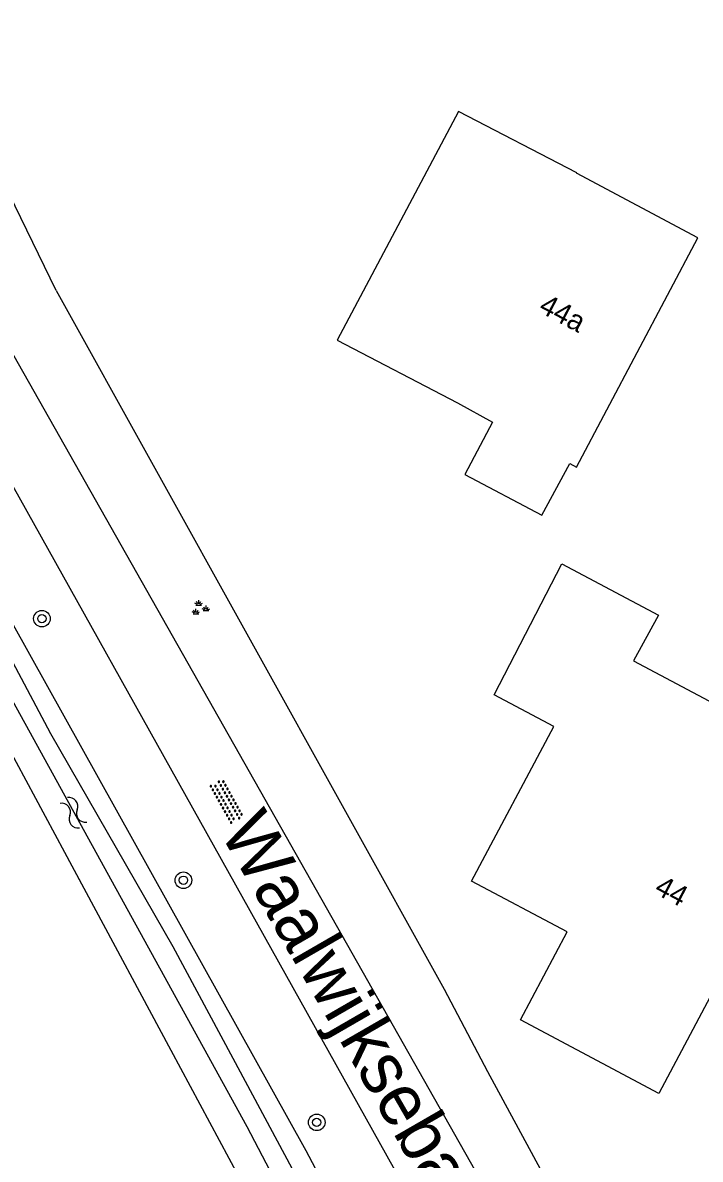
# Model space of a CAD drawing. Extents: x 136000 to 141000, y 400494 to 402006.
# Drawn here: x 137065.4 to 137098, y 400689.9 to 400744.6 of the extents above; entities that cross this region are included whole.
import ezdxf

# ---------------------------------------------------------------- set-up
doc = ezdxf.new("R2010")
doc.units = 0
for name, color, linetype in [('gg-afsc-erfafscheiding', 7, 'Continuous'), ('gg-afsc-hekwerk', 7, 'Continuous'), ('gg-anno-huisnummerreeks BGT', 7, 'Continuous'), ('gg-anno-openbare ruimte label', 7, 'Continuous'), ('gg-bbg-hoofdgebouw', 7, 'Continuous'), ('gg-knt-onverhard', 7, 'Continuous'), ('gg-kntw-bovenkant insteek waterloop', 7, 'Continuous'), ('gg-kntw-waterlijn', 7, 'Continuous'), ('gt-grn-groengrens', 7, 'Continuous'), ('gt-symb-boom', 7, 'Continuous'), ('gt-symb-groenvak', 7, 'Continuous'), ('gt-symb-overige verharding', 7, 'Continuous'), ('gt-symb-watersymbool', 7, 'Continuous')]:
    doc.layers.add(name, color=color, linetype=linetype)

# ---------------------------------------------------------------- blocks, each defined once
blk = doc.blocks.new('gt0-GRVAK')
at = {"layer": 'gt-symb-groenvak'}
for p, q in [((-0.11, 0.189), (-0.228, 0.24)), ((-0.182, 0.153), (0.088, 0.153)), ((-0.091, 0.211), (-0.156, 0.322)), ((-0.047, 0.214), (-0.047, 0.393)), ((-0.004, 0.211), (0.061, 0.322)), ((0.015, 0.189), (0.133, 0.24)), ((0.262, -0.052), (0.197, 0.059)), ((0.305, -0.049), (0.305, 0.13)), ((0.349, -0.052), (0.414, 0.059)), ((-0.245, -0.228), (-0.363, -0.177)), ((-0.318, -0.264), (-0.047, -0.264)), ((-0.226, -0.206), (-0.291, -0.095)), ((-0.183, -0.203), (-0.183, -0.024)), ((-0.139, -0.206), (-0.074, -0.095)), ((-0.12, -0.228), (-0.002, -0.177)), ((0.243, -0.074), (0.125, -0.023)), ((0.17, -0.11), (0.441, -0.11)), ((0.368, -0.074), (0.486, -0.023))]:
    blk.add_line(p, q, dxfattribs=at)
blk = doc.blocks.new('gt0-BOOM')
at = {"layer": 'gt-symb-boom'}
for radius in [0.4, 0.2]:
    blk.add_circle((0, 0), radius, dxfattribs=at)
blk = doc.blocks.new('gt0-WA')
at = {"layer": 'gt-symb-watersymbool'}
for centre, start, end in [((-0.323, 0.022), 28.0725, 151.9275), ((0.427, 0.422), 208.0725, 331.9275), ((-0.323, -0.428), 28.0725, 151.9275), ((0.427, -0.028), 208.0725, 331.9275)]:
    blk.add_arc(centre, 0.425, start, end, dxfattribs=at)
blk = doc.blocks.new('gt0-OVH')
at = {"layer": 'gt-symb-overige verharding'}
for points in [[(-0.972, 0.298), (-0.967, 0.308), (-0.965, 0.319), (-0.966, 0.33), (-0.971, 0.34), (-0.978, 0.348), (-0.988, 0.353), (-0.999, 0.355), (-1.01, 0.354), (-1.02, 0.349), (-1.028, 0.342), (-1.033, 0.332), (-1.035, 0.321), (-1.034, 0.31), (-1.029, 0.3), (-1.022, 0.292), (-1.012, 0.287), (-1.001, 0.285), (-0.99, 0.286), (-0.98, 0.291)], [(-0.872, 0.106), (-0.867, 0.116), (-0.865, 0.126), (-0.866, 0.137), (-0.871, 0.147), (-0.878, 0.156), (-0.888, 0.161), (-0.899, 0.163), (-0.91, 0.162), (-0.92, 0.157), (-0.928, 0.15), (-0.933, 0.14), (-0.935, 0.129), (-0.934, 0.118), (-0.929, 0.108), (-0.922, 0.1), (-0.912, 0.095), (-0.901, 0.092), (-0.89, 0.094), (-0.88, 0.098)], [(-0.772, 0.298), (-0.767, 0.308), (-0.765, 0.319), (-0.766, 0.33), (-0.771, 0.34), (-0.778, 0.348), (-0.788, 0.353), (-0.799, 0.355), (-0.81, 0.354), (-0.82, 0.349), (-0.828, 0.342), (-0.833, 0.332), (-0.835, 0.321), (-0.834, 0.31), (-0.829, 0.3), (-0.822, 0.292), (-0.812, 0.287), (-0.801, 0.285), (-0.79, 0.286), (-0.78, 0.291)], [(-0.672, 0.106), (-0.667, 0.116), (-0.665, 0.126), (-0.666, 0.137), (-0.671, 0.147), (-0.678, 0.156), (-0.688, 0.161), (-0.699, 0.163), (-0.71, 0.162), (-0.72, 0.157), (-0.728, 0.15), (-0.733, 0.14), (-0.735, 0.129), (-0.734, 0.118), (-0.729, 0.108), (-0.722, 0.1), (-0.712, 0.095), (-0.701, 0.092), (-0.69, 0.094), (-0.68, 0.098)], [(-0.572, 0.298), (-0.567, 0.308), (-0.565, 0.319), (-0.566, 0.33), (-0.571, 0.34), (-0.578, 0.348), (-0.588, 0.353), (-0.599, 0.355), (-0.61, 0.354), (-0.62, 0.349), (-0.628, 0.342), (-0.633, 0.332), (-0.635, 0.321), (-0.634, 0.31), (-0.629, 0.3), (-0.622, 0.292), (-0.612, 0.287), (-0.601, 0.285), (-0.59, 0.286), (-0.58, 0.291)], [(-0.472, 0.106), (-0.467, 0.116), (-0.465, 0.126), (-0.466, 0.137), (-0.471, 0.147), (-0.478, 0.156), (-0.488, 0.161), (-0.499, 0.163), (-0.51, 0.162), (-0.52, 0.157), (-0.528, 0.15), (-0.533, 0.14), (-0.535, 0.129), (-0.534, 0.118), (-0.529, 0.108), (-0.522, 0.1), (-0.512, 0.095), (-0.501, 0.092), (-0.49, 0.094), (-0.48, 0.098)], [(-0.372, 0.298), (-0.367, 0.308), (-0.365, 0.319), (-0.366, 0.33), (-0.371, 0.34), (-0.378, 0.348), (-0.388, 0.353), (-0.399, 0.355), (-0.41, 0.354), (-0.42, 0.349), (-0.428, 0.342), (-0.433, 0.332), (-0.435, 0.321), (-0.434, 0.31), (-0.429, 0.3), (-0.422, 0.292), (-0.412, 0.287), (-0.401, 0.285), (-0.39, 0.286), (-0.38, 0.291)], [(-0.272, 0.106), (-0.267, 0.116), (-0.265, 0.126), (-0.266, 0.137), (-0.271, 0.147), (-0.278, 0.156), (-0.288, 0.161), (-0.299, 0.163), (-0.31, 0.162), (-0.32, 0.157), (-0.328, 0.15), (-0.333, 0.14), (-0.335, 0.129), (-0.334, 0.118), (-0.329, 0.108), (-0.322, 0.1), (-0.312, 0.095), (-0.301, 0.092), (-0.29, 0.094), (-0.28, 0.098)], [(-0.172, 0.298), (-0.167, 0.308), (-0.165, 0.319), (-0.166, 0.33), (-0.171, 0.34), (-0.178, 0.348), (-0.188, 0.353), (-0.199, 0.355), (-0.21, 0.354), (-0.22, 0.349), (-0.228, 0.342), (-0.233, 0.332), (-0.235, 0.321), (-0.234, 0.31), (-0.229, 0.3), (-0.222, 0.292), (-0.212, 0.287), (-0.201, 0.285), (-0.19, 0.286), (-0.18, 0.291)], [(-0.072, 0.106), (-0.067, 0.116), (-0.065, 0.126), (-0.066, 0.137), (-0.071, 0.147), (-0.078, 0.156), (-0.088, 0.161), (-0.099, 0.163), (-0.11, 0.162), (-0.12, 0.157), (-0.128, 0.15), (-0.133, 0.14), (-0.135, 0.129), (-0.134, 0.118), (-0.129, 0.108), (-0.122, 0.1), (-0.112, 0.095), (-0.101, 0.092), (-0.09, 0.094), (-0.08, 0.098)], [(0.028, 0.298), (0.033, 0.308), (0.035, 0.319), (0.034, 0.33), (0.029, 0.34), (0.022, 0.348), (0.012, 0.353), (0.001, 0.355), (-0.01, 0.354), (-0.02, 0.349), (-0.028, 0.342), (-0.033, 0.332), (-0.035, 0.321), (-0.034, 0.31), (-0.029, 0.3), (-0.022, 0.292), (-0.012, 0.287), (-0.001, 0.285), (0.01, 0.286), (0.02, 0.291)], [(0.128, 0.106), (0.133, 0.116), (0.135, 0.126), (0.134, 0.137), (0.129, 0.147), (0.122, 0.156), (0.112, 0.161), (0.101, 0.163), (0.09, 0.162), (0.08, 0.157), (0.072, 0.15), (0.067, 0.14), (0.065, 0.129), (0.066, 0.118), (0.071, 0.108), (0.078, 0.1), (0.088, 0.095), (0.099, 0.092), (0.11, 0.094), (0.12, 0.098)], [(0.228, 0.298), (0.233, 0.308), (0.235, 0.319), (0.234, 0.33), (0.229, 0.34), (0.222, 0.348), (0.212, 0.353), (0.201, 0.355), (0.19, 0.354), (0.18, 0.349), (0.172, 0.342), (0.167, 0.332), (0.165, 0.321), (0.166, 0.31), (0.171, 0.3), (0.178, 0.292), (0.188, 0.287), (0.199, 0.285), (0.21, 0.286), (0.22, 0.291)], [(0.328, 0.106), (0.333, 0.116), (0.335, 0.126), (0.334, 0.137), (0.329, 0.147), (0.322, 0.156), (0.312, 0.161), (0.301, 0.163), (0.29, 0.162), (0.28, 0.157), (0.272, 0.15), (0.267, 0.14), (0.265, 0.129), (0.266, 0.118), (0.271, 0.108), (0.278, 0.1), (0.288, 0.095), (0.299, 0.092), (0.31, 0.094), (0.32, 0.098)], [(0.428, 0.298), (0.433, 0.308), (0.435, 0.319), (0.434, 0.33), (0.429, 0.34), (0.422, 0.348), (0.412, 0.353), (0.401, 0.355), (0.39, 0.354), (0.38, 0.349), (0.372, 0.342), (0.367, 0.332), (0.365, 0.321), (0.366, 0.31), (0.371, 0.3), (0.378, 0.292), (0.388, 0.287), (0.399, 0.285), (0.41, 0.286), (0.42, 0.291)], [(0.528, 0.106), (0.533, 0.116), (0.535, 0.126), (0.534, 0.137), (0.529, 0.147), (0.522, 0.156), (0.512, 0.161), (0.501, 0.163), (0.49, 0.162), (0.48, 0.157), (0.472, 0.15), (0.467, 0.14), (0.465, 0.129), (0.466, 0.118), (0.471, 0.108), (0.478, 0.1), (0.488, 0.095), (0.499, 0.092), (0.51, 0.094), (0.52, 0.098)], [(0.628, 0.298), (0.633, 0.308), (0.635, 0.319), (0.634, 0.33), (0.629, 0.34), (0.622, 0.348), (0.612, 0.353), (0.601, 0.355), (0.59, 0.354), (0.58, 0.349), (0.572, 0.342), (0.567, 0.332), (0.565, 0.321), (0.566, 0.31), (0.571, 0.3), (0.578, 0.292), (0.588, 0.287), (0.599, 0.285), (0.61, 0.286), (0.62, 0.291)], [(0.728, 0.106), (0.733, 0.116), (0.735, 0.126), (0.734, 0.137), (0.729, 0.147), (0.722, 0.156), (0.712, 0.161), (0.701, 0.163), (0.69, 0.162), (0.68, 0.157), (0.672, 0.15), (0.667, 0.14), (0.665, 0.129), (0.666, 0.118), (0.671, 0.108), (0.678, 0.1), (0.688, 0.095), (0.699, 0.092), (0.71, 0.094), (0.72, 0.098)], [(0.828, 0.298), (0.833, 0.308), (0.835, 0.319), (0.834, 0.33), (0.829, 0.34), (0.822, 0.348), (0.812, 0.353), (0.801, 0.355), (0.79, 0.354), (0.78, 0.349), (0.772, 0.342), (0.767, 0.332), (0.765, 0.321), (0.766, 0.31), (0.771, 0.3), (0.778, 0.292), (0.788, 0.287), (0.799, 0.285), (0.81, 0.286), (0.82, 0.291)], [(0.928, 0.106), (0.933, 0.116), (0.935, 0.126), (0.934, 0.137), (0.929, 0.147), (0.922, 0.156), (0.912, 0.161), (0.901, 0.163), (0.89, 0.162), (0.88, 0.157), (0.872, 0.15), (0.867, 0.14), (0.865, 0.129), (0.866, 0.118), (0.871, 0.108), (0.878, 0.1), (0.888, 0.095), (0.899, 0.092), (0.91, 0.094), (0.92, 0.098)], [(1.028, 0.298), (1.033, 0.308), (1.035, 0.319), (1.034, 0.33), (1.029, 0.34), (1.022, 0.348), (1.012, 0.353), (1.001, 0.355), (0.99, 0.354), (0.98, 0.349), (0.972, 0.342), (0.967, 0.332), (0.965, 0.321), (0.966, 0.31), (0.971, 0.3), (0.978, 0.292), (0.988, 0.287), (0.999, 0.285), (1.01, 0.286), (1.02, 0.291)], [(-0.972, -0.142), (-0.967, -0.132), (-0.965, -0.121), (-0.966, -0.11), (-0.971, -0.1), (-0.978, -0.092), (-0.988, -0.087), (-0.999, -0.085), (-1.01, -0.086), (-1.02, -0.091), (-1.028, -0.098), (-1.033, -0.108), (-1.035, -0.119), (-1.034, -0.13), (-1.029, -0.14), (-1.022, -0.148), (-1.012, -0.153), (-1.001, -0.155), (-0.99, -0.154), (-0.98, -0.149)], [(-0.872, -0.334), (-0.867, -0.324), (-0.865, -0.314), (-0.866, -0.303), (-0.871, -0.293), (-0.878, -0.284), (-0.888, -0.279), (-0.899, -0.277), (-0.91, -0.278), (-0.92, -0.283), (-0.928, -0.29), (-0.933, -0.3), (-0.935, -0.311), (-0.934, -0.322), (-0.929, -0.332), (-0.922, -0.34), (-0.912, -0.345), (-0.901, -0.348), (-0.89, -0.346), (-0.88, -0.342)], [(-0.772, -0.142), (-0.767, -0.132), (-0.765, -0.121), (-0.766, -0.11), (-0.771, -0.1), (-0.778, -0.092), (-0.788, -0.087), (-0.799, -0.085), (-0.81, -0.086), (-0.82, -0.091), (-0.828, -0.098), (-0.833, -0.108), (-0.835, -0.119), (-0.834, -0.13), (-0.829, -0.14), (-0.822, -0.148), (-0.812, -0.153), (-0.801, -0.155), (-0.79, -0.154), (-0.78, -0.149)], [(-0.672, -0.334), (-0.667, -0.324), (-0.665, -0.314), (-0.666, -0.303), (-0.671, -0.293), (-0.678, -0.284), (-0.688, -0.279), (-0.699, -0.277), (-0.71, -0.278), (-0.72, -0.283), (-0.728, -0.29), (-0.733, -0.3), (-0.735, -0.311), (-0.734, -0.322), (-0.729, -0.332), (-0.722, -0.34), (-0.712, -0.345), (-0.701, -0.348), (-0.69, -0.346), (-0.68, -0.342)], [(-0.572, -0.142), (-0.567, -0.132), (-0.565, -0.121), (-0.566, -0.11), (-0.571, -0.1), (-0.578, -0.092), (-0.588, -0.087), (-0.599, -0.085), (-0.61, -0.086), (-0.62, -0.091), (-0.628, -0.098), (-0.633, -0.108), (-0.635, -0.119), (-0.634, -0.13), (-0.629, -0.14), (-0.622, -0.148), (-0.612, -0.153), (-0.601, -0.155), (-0.59, -0.154), (-0.58, -0.149)], [(-0.472, -0.334), (-0.467, -0.324), (-0.465, -0.314), (-0.466, -0.303), (-0.471, -0.293), (-0.478, -0.284), (-0.488, -0.279), (-0.499, -0.277), (-0.51, -0.278), (-0.52, -0.283), (-0.528, -0.29), (-0.533, -0.3), (-0.535, -0.311), (-0.534, -0.322), (-0.529, -0.332), (-0.522, -0.34), (-0.512, -0.345), (-0.501, -0.348), (-0.49, -0.346), (-0.48, -0.342)], [(-0.372, -0.142), (-0.367, -0.132), (-0.365, -0.121), (-0.366, -0.11), (-0.371, -0.1), (-0.378, -0.092), (-0.388, -0.087), (-0.399, -0.085), (-0.41, -0.086), (-0.42, -0.091), (-0.428, -0.098), (-0.433, -0.108), (-0.435, -0.119), (-0.434, -0.13), (-0.429, -0.14), (-0.422, -0.148), (-0.412, -0.153), (-0.401, -0.155), (-0.39, -0.154), (-0.38, -0.149)], [(-0.272, -0.334), (-0.267, -0.324), (-0.265, -0.314), (-0.266, -0.303), (-0.271, -0.293), (-0.278, -0.284), (-0.288, -0.279), (-0.299, -0.277), (-0.31, -0.278), (-0.32, -0.283), (-0.328, -0.29), (-0.333, -0.3), (-0.335, -0.311), (-0.334, -0.322), (-0.329, -0.332), (-0.322, -0.34), (-0.312, -0.345), (-0.301, -0.348), (-0.29, -0.346), (-0.28, -0.342)], [(-0.172, -0.142), (-0.167, -0.132), (-0.165, -0.121), (-0.166, -0.11), (-0.171, -0.1), (-0.178, -0.092), (-0.188, -0.087), (-0.199, -0.085), (-0.21, -0.086), (-0.22, -0.091), (-0.228, -0.098), (-0.233, -0.108), (-0.235, -0.119), (-0.234, -0.13), (-0.229, -0.14), (-0.222, -0.148), (-0.212, -0.153), (-0.201, -0.155), (-0.19, -0.154), (-0.18, -0.149)], [(-0.072, -0.334), (-0.067, -0.324), (-0.065, -0.314), (-0.066, -0.303), (-0.071, -0.293), (-0.078, -0.284), (-0.088, -0.279), (-0.099, -0.277), (-0.11, -0.278), (-0.12, -0.283), (-0.128, -0.29), (-0.133, -0.3), (-0.135, -0.311), (-0.134, -0.322), (-0.129, -0.332), (-0.122, -0.34), (-0.112, -0.345), (-0.101, -0.348), (-0.09, -0.346), (-0.08, -0.342)], [(0.028, -0.142), (0.033, -0.132), (0.035, -0.121), (0.034, -0.11), (0.029, -0.1), (0.022, -0.092), (0.012, -0.087), (0.001, -0.085), (-0.01, -0.086), (-0.02, -0.091), (-0.028, -0.098), (-0.033, -0.108), (-0.035, -0.119), (-0.034, -0.13), (-0.029, -0.14), (-0.022, -0.148), (-0.012, -0.153), (-0.001, -0.155), (0.01, -0.154), (0.02, -0.149)], [(0.128, -0.334), (0.133, -0.324), (0.135, -0.314), (0.134, -0.303), (0.129, -0.293), (0.122, -0.284), (0.112, -0.279), (0.101, -0.277), (0.09, -0.278), (0.08, -0.283), (0.072, -0.29), (0.067, -0.3), (0.065, -0.311), (0.066, -0.322), (0.071, -0.332), (0.078, -0.34), (0.088, -0.345), (0.099, -0.348), (0.11, -0.346), (0.12, -0.342)], [(0.228, -0.142), (0.233, -0.132), (0.235, -0.121), (0.234, -0.11), (0.229, -0.1), (0.222, -0.092), (0.212, -0.087), (0.201, -0.085), (0.19, -0.086), (0.18, -0.091), (0.172, -0.098), (0.167, -0.108), (0.165, -0.119), (0.166, -0.13), (0.171, -0.14), (0.178, -0.148), (0.188, -0.153), (0.199, -0.155), (0.21, -0.154), (0.22, -0.149)], [(0.328, -0.334), (0.333, -0.324), (0.335, -0.314), (0.334, -0.303), (0.329, -0.293), (0.322, -0.284), (0.312, -0.279), (0.301, -0.277), (0.29, -0.278), (0.28, -0.283), (0.272, -0.29), (0.267, -0.3), (0.265, -0.311), (0.266, -0.322), (0.271, -0.332), (0.278, -0.34), (0.288, -0.345), (0.299, -0.348), (0.31, -0.346), (0.32, -0.342)], [(0.428, -0.142), (0.433, -0.132), (0.435, -0.121), (0.434, -0.11), (0.429, -0.1), (0.422, -0.092), (0.412, -0.087), (0.401, -0.085), (0.39, -0.086), (0.38, -0.091), (0.372, -0.098), (0.367, -0.108), (0.365, -0.119), (0.366, -0.13), (0.371, -0.14), (0.378, -0.148), (0.388, -0.153), (0.399, -0.155), (0.41, -0.154), (0.42, -0.149)], [(0.528, -0.334), (0.533, -0.324), (0.535, -0.314), (0.534, -0.303), (0.529, -0.293), (0.522, -0.284), (0.512, -0.279), (0.501, -0.277), (0.49, -0.278), (0.48, -0.283), (0.472, -0.29), (0.467, -0.3), (0.465, -0.311), (0.466, -0.322), (0.471, -0.332), (0.478, -0.34), (0.488, -0.345), (0.499, -0.348), (0.51, -0.346), (0.52, -0.342)], [(0.628, -0.142), (0.633, -0.132), (0.635, -0.121), (0.634, -0.11), (0.629, -0.1), (0.622, -0.092), (0.612, -0.087), (0.601, -0.085), (0.59, -0.086), (0.58, -0.091), (0.572, -0.098), (0.567, -0.108), (0.565, -0.119), (0.566, -0.13), (0.571, -0.14), (0.578, -0.148), (0.588, -0.153), (0.599, -0.155), (0.61, -0.154), (0.62, -0.149)], [(0.728, -0.334), (0.733, -0.324), (0.735, -0.314), (0.734, -0.303), (0.729, -0.293), (0.722, -0.284), (0.712, -0.279), (0.701, -0.277), (0.69, -0.278), (0.68, -0.283), (0.672, -0.29), (0.667, -0.3), (0.665, -0.311), (0.666, -0.322), (0.671, -0.332), (0.678, -0.34), (0.688, -0.345), (0.699, -0.348), (0.71, -0.346), (0.72, -0.342)], [(0.828, -0.142), (0.833, -0.132), (0.835, -0.121), (0.834, -0.11), (0.829, -0.1), (0.822, -0.092), (0.812, -0.087), (0.801, -0.085), (0.79, -0.086), (0.78, -0.091), (0.772, -0.098), (0.767, -0.108), (0.765, -0.119), (0.766, -0.13), (0.771, -0.14), (0.778, -0.148), (0.788, -0.153), (0.799, -0.155), (0.81, -0.154), (0.82, -0.149)], [(0.928, -0.334), (0.933, -0.324), (0.935, -0.314), (0.934, -0.303), (0.929, -0.293), (0.922, -0.284), (0.912, -0.279), (0.901, -0.277), (0.89, -0.278), (0.88, -0.283), (0.872, -0.29), (0.867, -0.3), (0.865, -0.311), (0.866, -0.322), (0.871, -0.332), (0.878, -0.34), (0.888, -0.345), (0.899, -0.348), (0.91, -0.346), (0.92, -0.342)], [(1.028, -0.142), (1.033, -0.132), (1.035, -0.121), (1.034, -0.11), (1.029, -0.1), (1.022, -0.092), (1.012, -0.087), (1.001, -0.085), (0.99, -0.086), (0.98, -0.091), (0.972, -0.098), (0.967, -0.108), (0.965, -0.119), (0.966, -0.13), (0.971, -0.14), (0.978, -0.148), (0.988, -0.153), (0.999, -0.155), (1.01, -0.154), (1.02, -0.149)]]:
    blk.add_lwpolyline(points, close=True, dxfattribs=at)

msp = doc.modelspace()

# ---------------------------------------------------------------- linework, layer by layer
at = {"layer": 'gg-afsc-erfafscheiding'}
for p, q in [((137067.029, 400731.68), (137085.715, 400698.035)), ((137087.809, 400694.083), (137093.303, 400683.93))]:
    msp.add_line(p, q, dxfattribs=at)
at = {"layer": 'gg-afsc-hekwerk'}
msp.add_line((137085.715, 400698.035), (137087.809, 400694.083), dxfattribs=at)
msp.add_line((137085.715, 400698.035), (137087.809, 400694.083), dxfattribs=at)
at = {"layer": 'gg-bbg-hoofdgebouw'}
for points in [[(137092.094, 400737.315), (137092.103, 400737.333), (137086.403, 400740.289), (137080.571, 400729.277), (137086.367, 400726.271)], [(137090.426, 400720.863), (137091.766, 400723.344), (137092.084, 400723.175), (137097.936, 400734.208), (137092.094, 400737.315)], [(137086.367, 400726.271), (137088.043, 400725.334), (137086.705, 400722.822), (137090.426, 400720.863)], [(137088.124, 400712.204), (137091.387, 400718.52), (137096.035, 400716.043), (137094.841, 400713.842), (137104.412, 400708.758), (137096.061, 400693.012), (137089.396, 400696.571)], [(137089.396, 400696.571), (137091.642, 400700.794), (137087.038, 400703.242), (137090.992, 400710.679), (137088.124, 400712.204)]]:
    msp.add_lwpolyline(points, dxfattribs=at)
at = {"layer": 'gg-knt-onverhard'}
for points in [[(137000, 400823.96), (137052.822, 400750), (137090.68, 400683.191)], [(137000, 400818.181), (137051.42, 400746.472), (137087.782, 400681.37)]]:
    msp.add_lwpolyline(points, dxfattribs=at)
at = {"layer": 'gg-kntw-bovenkant insteek waterloop'}
for points in [[(137085.81, 400670.117), (137088.609, 400672.21), (137079.08, 400690.264), (137059.918, 400724.619), (137047.311, 400743.592)], [(137044.241, 400741.599), (137057.119, 400722.526), (137064.646, 400709.828), (137076.281, 400688.171), (137085.81, 400670.117)]]:
    msp.add_lwpolyline(points, dxfattribs=at)
at = {"layer": 'gg-kntw-waterlijn'}
msp.add_lwpolyline([(137045.917, 400741.767), (137052.467, 400732.405), (137061.311, 400718.491), (137076.212, 400691.424), (137086.53, 400671.701), (137087.506, 400672.438), (137083.862, 400679.23), (137075.561, 400694.705), (137072.673, 400700.087), (137066.784, 400710.334), (137062.12, 400719.072), (137055.722, 400729.073), (137051.5, 400735.672), (137046.868, 400742.375), (137045.917, 400741.767)], dxfattribs=at)
at = {"layer": 'gt-grn-groengrens'}
msp.add_line((137067.029, 400731.68), (137061.893, 400742.209), dxfattribs=at)

# ---------------------------------------------------------------- block references
at = {"layer": 'gt-symb-boom'}
for p in [(137066.349, 400715.877), (137073.162, 400703.284), (137079.579, 400691.631)]:
    msp.add_blockref('gt0-BOOM', p, dxfattribs=at)
at = {"layer": 'gt-symb-groenvak'}
msp.add_blockref('gt0-GRVAK', (137073.946, 400716.376), dxfattribs=at)
at = {"layer": 'gt-symb-overige verharding', "rotation": 119.12691210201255}
msp.add_blockref('gt0-OVH', (137075.251, 400707.092), dxfattribs=at)
at = {"layer": 'gt-symb-watersymbool', "rotation": -51.82346239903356}
msp.add_blockref('gt0-WA', (137067.835, 400706.578), dxfattribs=at)

# ---------------------------------------------------------------- texts
at = {"layer": 'gg-anno-huisnummerreeks BGT'}
for s, rotation, p in [('44a', 332.1, (137090.212, 400730.669)), ('44', 332, (137095.782, 400702.682))]:
    msp.add_text(s, height=1, rotation=rotation, dxfattribs=at).set_placement(p)
at = {"layer": 'gg-anno-openbare ruimte label'}
msp.add_text('Waalwijksebaan', height=2.5, rotation=300, dxfattribs=at).set_placement((137074.862, 400705.639))

doc.saveas('drawing.dxf')
